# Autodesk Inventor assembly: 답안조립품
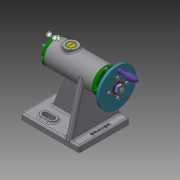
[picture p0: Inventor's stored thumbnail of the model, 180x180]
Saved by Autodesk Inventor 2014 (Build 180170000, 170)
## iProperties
Created: 2019-10
Part Number: 답안조립품
Document SubType Name: Assembly
Designer: kh
Author: kh
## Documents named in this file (18)
- C:\Users\kh\Desktop\491004V1009\답안조립품.iam
- C:\Users\kh\Desktop\491004V1009\본체.ipt
- C:\Users\kh\Desktop\491004V1009\나사.ipt
- C:\Users\kh\Desktop\491004V1009\나사축.ipt
- C:\Users\kh\Desktop\491004V1009\너트 M8.ipt
- C:\Users\kh\Desktop\491004V1009\돌림판.ipt
- C:\Users\kh\Desktop\491004V1009\멈춤나사 M3.ipt
- C:\Users\kh\Desktop\491004V1009\볼트 M3.ipt
- C:\Users\kh\Desktop\491004V1009\부시.ipt
- C:\Users\kh\Desktop\491004V1009\센터.ipt
- C:\Users\kh\Desktop\491004V1009\센터홀더.ipt
- C:\Users\kh\Desktop\491004V1009\슬리브.ipt
- C:\Users\kh\Desktop\491004V1009\와셔.ipt
- C:\Users\kh\Desktop\491004V1009\중공축.ipt
- C:\Users\kh\Desktop\491004V1009\커버.ipt
- C:\Users\kh\Desktop\491004V1009\키 4 x 4 x 10.ipt
- C:\Users\kh\Desktop\491004V1009\플랜지.ipt
- C:\Users\kh\Desktop\491004V1009\핸들.ipt
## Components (2 placed, 2 different names)
1. 플랜지:1 — Insert:13, Insert:15, Mate:2, Insert:24
2. 핸들:1 — Insert:25
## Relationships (5: Insert 4, Mate 1)
- Insert:13: 플랜지:1
- Insert:15: 플랜지:1
- Mate:2: 플랜지:1
- Insert:24: 플랜지:1
- Insert:25: 핸들:1
